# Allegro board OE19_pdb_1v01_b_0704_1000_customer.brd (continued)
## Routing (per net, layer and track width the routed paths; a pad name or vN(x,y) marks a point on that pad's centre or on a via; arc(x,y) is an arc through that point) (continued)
DELTA_L_85_10INCH_IN1_DN: length 254
  IN1 w0.114: v1(215.42,159.29) 215.56,159.43 215.56,161.63 216.19,162.26 216.56,164.33 216.44,164.5 212.99,165.11 212.69,165.53 212.87,166.52 213.29,166.82 217.24,166.12 217.37,166.22 217.49,166.86 217.39,166.99 213.14,167.74 212.85,168.16 213.02,169.15 213.45,169.44 217.64,168.71 217.77,168.8 217.88,169.44 217.79,169.58 213.21,170.38 212.91,170.8 213.12,171.96 213.54,172.26 217.61,171.54 217.74,171.63 217.86,172.27 217.76,172.4 213.1,173.23 212.81,173.65 212.98,174.64 213.4,174.93 217.61,174.19 217.75,174.28 217.86,174.92 217.77,175.06 213.22,175.86 212.93,176.28 213.1,177.27 213.52,177.56 217.6,176.85 217.73,176.94 217.84,177.58 217.75,177.71 213.19,178.52 212.9,178.94 213.07,179.93 213.49,180.22 217.58,179.5 217.71,179.59 217.83,180.23 217.73,180.37 213.24,181.16 212.94,181.58 213.12,182.57 213.54,182.87 217.62,182.15 217.75,182.24 217.87,182.88 217.77,183.01 213.24,183.81 212.95,184.23 213.12,185.22 213.54,185.52 217.64,184.8 217.77,184.89 217.89,185.53 217.79,185.66 213.18,186.48 212.88,186.9 213.06,187.89 213.48,188.18 217.58,187.46 217.71,187.55 217.83,188.19 217.74,188.32 213.17,189.13 212.88,189.55 213.05,190.54 213.48,190.84 217.64,190.1 217.77,190.19 217.88,190.84 217.79,190.97 213.19,191.78 212.89,192.2 213.07,193.19 213.49,193.49 217.52,192.77 217.66,192.87 217.77,193.51 217.68,193.64 213.16,194.44 212.87,194.86 213.04,195.85 213.47,196.14 217.56,195.42 217.69,195.51 217.8,196.15 217.71,196.29 213.19,197.08 212.9,197.51 213.07,198.49 213.49,198.79 217.59,198.07 217.72,198.16 217.83,198.8 217.74,198.93 213.22,199.73 212.93,200.15 213.1,201.14 213.52,201.44 217.63,200.71 217.76,200.81 217.88,201.45 217.78,201.58 213.23,202.38 212.93,202.8 213.11,203.79 213.53,204.09 217.62,203.37 217.75,203.46 217.87,204.1 217.78,204.23 213.22,205.04 212.92,205.46 213.1,206.45 213.52,206.74 217.52,206.04 217.65,206.13 217.77,206.77 217.67,206.9 213.19,207.69 212.9,208.11 213.07,209.1 213.5,209.4 217.59,208.68 217.72,208.77 217.84,209.41 217.75,209.54 213.18,210.35 212.89,210.77 213.06,211.76 213.48,212.05 217.61,211.33 217.75,211.42 217.86,212.06 217.77,212.19 213.17,213 212.87,213.42 213.05,214.41 213.47,214.71 217.59,213.98 217.72,214.08 217.84,214.72 217.74,214.85 213.17,215.66 212.87,216.08 213.05,217.07 213.47,217.36 217.55,216.64 217.68,216.74 217.79,217.38 217.7,217.51 213.17,218.31 212.88,218.73 213.05,219.72 213.48,220.01 215.32,219.69 215.45,219.78 215.59,220.57 215.59,223.11 v1(215.41,223.28)
  BOTTOM w0.099: J27.1 v1(215.41,223.28) ; J33.2 v1(215.42,159.29)
DELTA_L_85_10INCH_IN1_DP: length 254
  IN1 w0.114: v1(216.18,159.29) 215.99,159.48 215.99,161.45 216.59,162.05 217.01,164.43 216.69,164.89 213.24,165.5 213.14,165.63 213.26,166.28 213.39,166.37 217.34,165.67 217.76,165.97 217.94,166.96 217.64,167.38 213.39,168.13 213.3,168.26 213.41,168.9 213.55,168.99 217.74,168.25 218.16,168.55 218.33,169.54 218.04,169.96 213.46,170.77 213.37,170.9 213.51,171.71 213.64,171.81 217.71,171.09 218.13,171.38 218.31,172.37 218.01,172.79 213.35,173.62 213.26,173.75 213.37,174.39 213.5,174.48 217.71,173.74 218.14,174.04 218.31,175.02 218.01,175.45 213.47,176.25 213.38,176.38 213.49,177.02 213.62,177.11 217.7,176.4 218.12,176.69 218.29,177.68 218,178.1 213.44,178.91 213.35,179.04 213.46,179.68 213.59,179.77 217.68,179.05 218.1,179.35 218.28,180.33 217.98,180.76 213.49,181.55 213.39,181.68 213.51,182.32 213.64,182.42 217.72,181.7 218.14,181.99 218.32,182.98 218.02,183.4 213.49,184.2 213.4,184.33 213.51,184.97 213.64,185.07 217.74,184.35 218.16,184.64 218.34,185.63 218.04,186.05 213.43,186.87 213.33,187 213.45,187.64 213.58,187.73 217.68,187.01 218.1,187.3 218.28,188.29 217.98,188.71 213.42,189.52 213.33,189.65 213.44,190.29 213.58,190.38 217.74,189.65 218.16,189.95 218.34,190.94 218.04,191.36 213.44,192.17 213.34,192.3 213.46,192.94 213.59,193.04 217.62,192.32 218.05,192.62 218.22,193.61 217.93,194.03 213.41,194.83 213.32,194.96 213.43,195.6 213.57,195.69 217.66,194.97 218.08,195.27 218.25,196.25 217.96,196.68 213.44,197.47 213.35,197.61 213.46,198.25 213.59,198.34 217.69,197.62 218.11,197.91 218.29,198.9 217.99,199.32 213.47,200.12 213.38,200.25 213.49,200.89 213.62,200.99 217.73,200.26 218.15,200.56 218.33,201.55 218.03,201.97 213.48,202.77 213.39,202.9 213.5,203.55 213.63,203.64 217.72,202.92 218.14,203.21 218.32,204.2 218.02,204.62 213.46,205.43 213.37,205.56 213.49,206.2 213.62,206.29 217.62,205.59 218.04,205.88 218.22,206.87 217.92,207.29 213.44,208.08 213.35,208.21 213.46,208.86 213.6,208.95 217.69,208.23 218.11,208.52 218.29,209.51 217.99,209.93 213.43,210.74 213.34,210.87 213.45,211.51 213.58,211.6 217.71,210.88 218.14,211.17 218.31,212.16 218.02,212.58 213.42,213.39 213.32,213.52 213.44,214.17 213.57,214.26 217.69,213.53 218.11,213.83 218.29,214.82 217.99,215.24 213.42,216.05 213.32,216.18 213.44,216.82 213.57,216.91 217.65,216.19 218.07,216.49 218.24,217.48 217.95,217.9 213.42,218.7 213.33,218.83 213.44,219.47 213.58,219.56 215.42,219.24 215.84,219.53 216.02,220.53 216.02,223.13 v1(216.18,223.28)
  BOTTOM w0.099: J33.1 v1(216.18,159.29) ; J27.2 v1(216.18,223.28)
DELTA_L_85_10INCH_IN2_DN: length 254
  TOP w0.099: J31.2 v1(213.64,159.52) ; J25.1 v1(213.64,223.09)
  IN2 w0.114: v1(213.64,223.09) 213.47,222.93 213.47,220.82 213.65,219.77 213.79,219.68 215.63,220 216.05,219.71 216.22,218.72 215.93,218.29 211.4,217.5 211.31,217.36 211.43,216.72 211.56,216.63 215.63,217.35 216.06,217.05 216.23,216.06 215.94,215.64 211.36,214.84 211.27,214.7 211.38,214.06 211.51,213.97 215.63,214.7 216.05,214.4 216.23,213.41 215.93,212.99 211.34,212.18 211.24,212.05 211.36,211.41 211.49,211.31 215.62,212.04 216.04,211.75 216.22,210.76 215.92,210.34 211.36,209.53 211.27,209.4 211.38,208.76 211.51,208.66 215.61,209.39 216.03,209.09 216.2,208.1 215.91,207.68 211.43,206.89 211.34,206.76 211.45,206.12 211.58,206.02 215.59,206.73 216.01,206.44 216.18,205.45 215.89,205.02 211.33,204.22 211.24,204.09 211.35,203.45 211.48,203.35 215.57,204.08 215.99,203.78 216.17,202.79 215.87,202.37 211.32,201.57 211.23,201.43 211.34,200.79 211.47,200.7 215.58,201.42 216,201.13 216.18,200.14 215.88,199.72 211.36,198.92 211.27,198.79 211.38,198.15 211.51,198.06 215.61,198.78 216.03,198.48 216.21,197.49 215.91,197.07 211.39,196.27 211.3,196.14 211.41,195.5 211.55,195.41 215.64,196.13 216.06,195.83 216.23,194.84 215.94,194.42 211.43,193.63 211.33,193.49 211.45,192.85 211.58,192.76 215.62,193.47 216.04,193.18 216.21,192.19 215.92,191.77 211.31,190.95 211.22,190.82 211.33,190.18 211.46,190.09 215.63,190.82 216.05,190.53 216.22,189.54 215.93,189.12 211.37,188.31 211.28,188.18 211.39,187.54 211.52,187.45 215.62,188.17 216.05,187.87 216.22,186.88 215.93,186.46 211.31,185.65 211.22,185.52 211.33,184.88 211.46,184.78 215.56,185.51 215.98,185.21 216.16,184.22 215.86,183.8 211.33,183 211.24,182.87 211.35,182.23 211.48,182.13 215.56,182.85 215.99,182.56 216.16,181.57 215.87,181.15 211.37,180.35 211.28,180.22 211.39,179.58 211.52,179.49 215.61,180.21 216.03,179.91 216.21,178.92 215.91,178.5 211.35,177.7 211.26,177.57 211.37,176.93 211.51,176.83 215.58,177.55 216,177.26 216.18,176.27 215.88,175.84 211.37,175.05 211.28,174.92 211.39,174.28 211.53,174.18 215.61,174.91 216.04,174.61 216.21,173.62 215.92,173.2 211.37,172.4 211.28,172.27 211.39,171.62 211.53,171.53 215.56,172.24 215.98,171.95 216.19,170.79 215.89,170.37 211.31,169.56 211.22,169.43 211.33,168.79 211.47,168.69 215.72,169.44 216.14,169.15 216.17,168.97 216.31,168.16 216.02,167.74 211.77,166.99 211.68,166.85 211.79,166.21 211.92,166.12 215.84,166.81 216.26,166.52 216.44,165.53 216.14,165.1 212.43,164.45 212.34,164.32 212.66,162.48 213.47,161.67 213.47,159.69 v1(213.64,159.52)
DELTA_L_85_10INCH_IN2_DP: length 254
  TOP w0.099: J25.2 v1(212.87,223.09) ; J31.1 v1(212.88,159.52)
  IN2 w0.114: v1(212.88,159.52) 213.04,159.69 213.04,161.5 212.26,162.28 211.89,164.42 212.18,164.84 215.89,165.49 215.99,165.63 215.87,166.27 215.74,166.36 211.82,165.67 211.4,165.96 211.22,166.95 211.52,167.38 215.77,168.12 215.86,168.26 215.75,168.9 215.62,168.99 211.37,168.24 210.94,168.54 210.77,169.53 211.06,169.95 215.64,170.76 215.74,170.89 215.59,171.7 215.46,171.79 211.43,171.08 211,171.38 210.83,172.37 211.13,172.79 215.67,173.59 215.76,173.72 215.65,174.36 215.51,174.45 211.43,173.73 211,174.03 210.83,175.02 211.13,175.44 215.63,176.23 215.72,176.37 215.61,177.01 215.48,177.1 211.41,176.38 210.98,176.68 210.81,177.67 211.11,178.09 215.66,178.89 215.75,179.02 215.64,179.67 215.51,179.76 211.42,179.04 211,179.33 210.82,180.32 211.12,180.74 215.62,181.54 215.71,181.67 215.6,182.31 215.46,182.4 211.38,181.68 210.96,181.98 210.78,182.97 211.08,183.39 215.61,184.19 215.7,184.32 215.59,184.96 215.46,185.05 211.36,184.33 210.94,184.63 210.77,185.62 211.06,186.04 215.68,186.85 215.77,186.98 215.66,187.63 215.52,187.72 211.42,187 211,187.29 210.82,188.28 211.12,188.7 215.68,189.51 215.77,189.64 215.66,190.28 215.53,190.37 211.36,189.64 210.94,189.93 210.77,190.92 211.06,191.34 215.67,192.16 215.76,192.29 215.65,192.93 215.52,193.02 211.48,192.31 211.06,192.61 210.88,193.59 211.18,194.02 215.69,194.81 215.78,194.94 215.67,195.59 215.54,195.68 211.45,194.96 211.03,195.25 210.85,196.24 211.15,196.66 215.66,197.46 215.76,197.59 215.64,198.23 215.51,198.33 211.41,197.6 210.99,197.9 210.82,198.89 211.11,199.31 215.63,200.11 215.73,200.24 215.61,200.88 215.48,200.97 211.37,200.25 210.95,200.54 210.77,201.53 211.07,201.96 215.63,202.76 215.72,202.89 215.61,203.53 215.47,203.62 211.38,202.9 210.96,203.2 210.78,204.19 211.08,204.61 215.64,205.41 215.73,205.55 215.62,206.19 215.49,206.28 211.48,205.57 211.06,205.87 210.88,206.86 211.18,207.28 215.66,208.07 215.75,208.2 215.64,208.84 215.51,208.94 211.41,208.21 210.99,208.51 210.81,209.5 211.11,209.92 215.67,210.73 215.77,210.86 215.65,211.5 215.52,211.59 211.39,210.86 210.97,211.16 210.79,212.15 211.09,212.57 215.69,213.38 215.78,213.51 215.67,214.15 215.53,214.25 211.41,213.52 210.99,213.81 210.82,214.8 211.11,215.23 215.69,216.03 215.78,216.16 215.67,216.81 215.53,216.9 211.46,216.18 211.04,216.48 210.86,217.46 211.16,217.89 215.68,218.68 215.77,218.82 215.66,219.46 215.53,219.55 213.69,219.22 213.26,219.52 213.04,220.78 213.04,222.93 v1(212.87,223.09)
DELTA_L_85_10INCH_TOP_DN: length 254
  TOP w0.099: J26.1 213.04,240.82 213.04,244.24 213.62,244.83 213.99,244.89 214.07,245.01 213.95,245.66 213.84,245.74 211.02,245.24 210.66,245.49 210.5,246.44 210.75,246.79 215.48,247.63 215.56,247.74 215.44,248.4 215.33,248.48 211.05,247.72 210.7,247.97 210.53,248.92 210.78,249.27 215.44,250.09 215.52,250.21 215.4,250.86 215.29,250.94 211.05,250.19 210.7,250.44 210.53,251.39 210.78,251.74 215.47,252.57 215.55,252.68 215.43,253.34 215.32,253.42 211,252.66 210.65,252.91 210.48,253.85 210.73,254.21 215.49,255.05 215.57,255.16 215.45,255.82 215.34,255.9 211.03,255.14 210.68,255.39 210.51,256.33 210.76,256.68 215.45,257.51 215.53,257.63 215.41,258.28 215.3,258.36 211.01,257.61 210.65,257.85 210.49,258.8 210.73,259.15 215.47,259.99 215.55,260.1 215.44,260.76 215.32,260.84 211.04,260.08 210.69,260.33 210.52,261.28 210.77,261.63 215.49,262.46 215.57,262.58 215.45,263.23 215.34,263.31 211.06,262.56 210.7,262.81 210.54,263.75 210.78,264.11 215.49,264.94 215.57,265.05 215.46,265.71 215.34,265.79 211.02,265.03 210.66,265.27 210.5,266.22 210.75,266.57 215.5,267.41 215.58,267.52 215.46,268.18 215.35,268.26 211.01,267.5 210.66,267.75 210.49,268.69 210.74,269.04 215.45,269.87 215.53,269.99 215.41,270.64 215.3,270.73 211.05,269.98 210.69,270.22 210.53,271.17 210.78,271.52 215.45,272.35 215.53,272.46 215.41,273.12 215.3,273.2 211.07,272.45 210.71,272.7 210.54,273.65 210.79,274 215.45,274.82 215.53,274.93 215.41,275.59 215.3,275.67 211.02,274.92 210.67,275.16 210.5,276.11 210.75,276.46 215.44,277.29 215.52,277.41 215.41,278.06 215.29,278.14 211.05,277.39 210.7,277.64 210.53,278.59 210.78,278.94 215.48,279.77 215.56,279.88 215.44,280.54 215.33,280.62 211.05,279.87 210.69,280.11 210.53,281.06 210.77,281.41 215.44,282.24 215.52,282.35 215.4,283.01 215.29,283.09 211.06,282.34 210.71,282.59 210.54,283.53 210.79,283.89 215.43,284.71 215.51,284.82 215.39,285.48 215.28,285.56 211.05,284.81 210.7,285.06 210.61,285.53 210.53,286.01 210.78,286.36 215.48,287.19 215.56,287.3 215.44,287.96 215.33,288.04 211.06,287.29 210.7,287.53 210.62,288.01 210.54,288.48 210.78,288.83 215.49,289.66 215.57,289.78 215.45,290.43 215.34,290.51 211.07,289.76 210.72,290.01 210.63,290.48 210.55,290.95 210.8,291.31 215.45,292.13 215.53,292.24 215.42,292.9 215.3,292.98 211.09,292.24 210.73,292.48 210.57,293.43 210.81,293.78 215.45,294.6 215.55,294.74 215.44,295.36 215.3,295.45 213.41,295.12 211.52,294.79 211.17,295.03 211,295.98 211.25,296.33 213.09,296.66 213.17,296.77 213.04,297.51 213.04,300.61 J32.2
DELTA_L_85_10INCH_TOP_DP: length 254
  TOP w0.099: J26.2 213.39,240.82 213.39,244.1 213.8,244.5 214.19,244.57 214.44,244.92 214.28,245.87 213.92,246.11 211.1,245.62 210.99,245.7 210.87,246.35 210.95,246.47 215.68,247.3 215.93,247.66 215.77,248.6 215.41,248.85 211.14,248.1 211.02,248.18 210.91,248.83 210.99,248.95 215.64,249.77 215.89,250.12 215.72,251.07 215.37,251.32 211.13,250.57 211.02,250.65 210.9,251.31 210.98,251.42 215.68,252.25 215.92,252.6 215.76,253.55 215.4,253.79 211.09,253.03 210.97,253.11 210.86,253.77 210.94,253.88 215.69,254.72 215.94,255.08 215.77,256.02 215.42,256.27 211.11,255.51 211,255.59 210.94,255.92 210.88,256.25 210.96,256.36 215.66,257.19 215.9,257.54 215.74,258.49 215.38,258.74 211.09,257.98 210.98,258.06 210.86,258.72 210.94,258.83 215.68,259.67 215.93,260.02 215.76,260.96 215.41,261.21 211.12,260.46 211.01,260.54 210.89,261.19 210.97,261.31 215.69,262.14 215.94,262.5 215.78,263.44 215.42,263.69 211.14,262.93 211.03,263.01 210.91,263.67 210.99,263.78 215.7,264.61 215.94,264.97 215.78,265.91 215.42,266.16 211.1,265.4 210.99,265.48 210.87,266.14 210.95,266.25 215.7,267.09 215.95,267.44 215.78,268.39 215.43,268.63 211.1,267.87 210.98,267.95 210.87,268.61 210.95,268.72 215.65,269.55 215.9,269.91 215.74,270.85 215.38,271.1 211.13,270.35 211.02,270.43 210.9,271.09 210.98,271.2 215.65,272.02 215.9,272.38 215.73,273.32 215.38,273.57 211.15,272.82 211.03,272.9 210.92,273.56 211,273.68 215.66,274.5 215.9,274.85 215.74,275.8 215.38,276.04 211.11,275.29 210.99,275.37 210.88,276.03 210.96,276.14 215.65,276.97 215.9,277.32 215.73,278.27 215.38,278.52 211.13,277.77 211.02,277.85 210.9,278.5 210.98,278.62 215.68,279.45 215.93,279.8 215.77,280.75 215.41,280.99 211.13,280.24 211.02,280.32 210.9,280.98 210.98,281.09 215.64,281.91 215.89,282.27 215.72,283.21 215.37,283.46 211.15,282.71 211.03,282.79 210.92,283.45 211,283.57 215.63,284.38 215.88,284.74 215.71,285.68 215.36,285.93 211.13,285.19 211.02,285.27 210.9,285.92 210.98,286.04 215.68,286.87 215.93,287.22 215.77,288.16 215.41,288.41 211.14,287.66 211.03,287.74 210.91,288.4 210.99,288.51 215.69,289.34 215.94,289.69 215.77,290.64 215.42,290.89 211.15,290.13 211.04,290.21 210.92,290.87 211,290.98 215.66,291.81 215.91,292.16 215.74,293.1 215.38,293.35 211.17,292.61 211.05,292.69 210.94,293.35 211.02,293.46 215.66,294.28 215.92,294.65 215.76,295.56 215.39,295.83 211.61,295.16 211.49,295.24 211.38,295.9 211.46,296.01 213.29,296.33 213.54,296.69 213.39,297.54 213.39,300.61 J32.1
FM_BBU_PRSNT_N: length 155
  IN2 w0.127: J1.B7 189.31,149.15 189.31,126.48 155.37,92.54 v1(155.37,24.02) 155.57,24.02 163.46,16.13 163.46,14.04 J9.I8
FM_BMC_SLED1_READY_N: length 155.5
  IN1 w0.127: J1.C8 189.74,147.9 189.74,124.91 165.51,100.68 v1(165.51,67.47) 165.51,67.08 165.03,66.6 165.03,65.32 162.56,62.85 162.56,28.53 167.48,23.61 167.48,20.63 168.89,19.23 168.89,8.76 168.88,8.75 168.88,8.18 J9.E6
FM_BMC_SLED2_READY_N: length 149
  IN1 w0.127: J1.H3 179.72,140.78 179.72,135.11 157.12,112.51 157.12,24.29 v1(159.58,21.83)
  BOTTOM w0.114: J9.F6 167.18,10.12 167.18,17.93 163.28,21.83 v1(159.58,21.83)
FM_BMC_SLED3_READY_N: length 153.4
  IN2 w0.127: v1(161.52,27.54) 156.87,32.18 156.87,92 191.27,126.39 191.27,143.69 J1.F8
  BOTTOM w0.114: J9.G6 167.45,11.25 167.45,20.01 162.89,24.57 162.89,26.17 v1(161.52,27.54)
FM_BMC_SLED4_READY_N: length 142.3
  IN1 w0.127: v1(180.57,132.19) 180.57,130.3 180.94,129.92 180.94,126.9 157.98,103.94 v1(157.98,28.94)
  BOTTOM w0.114: J1.K3 181.13,136.73 181.13,133.89 180.57,133.32 v1(180.57,132.19) ; J9.H6 167.71,12.39 167.71,20.54 167.7,20.57 164.82,23.45 164.82,25.98 161.86,28.94 v1(157.98,28.94)
FM_BMC_SLED5_READY_N: length 141
  IN1 w0.127: v1(164.31,28.36) 163.46,29.21 163.46,61.43 184.46,82.43 v1(184.46,113.53)
  IN2 w0.127: v1(164.31,28.36) 165.05,27.63 165.05,24.08 169.2,19.93 169.2,14.1 J9.I6
  BOTTOM w0.114: J1.I8 189.67,139.43 189.67,133.38 189.4,132.8 184.46,127.86 v1(184.46,113.53)
FM_PSU1_PRSNT_N: length 23.9
  TOP w0.114: J9.G8 163.72,10.4 160.87,13.24 160.87,16.54 158.18,19.24 149.61,19.24 147.87,20.97 R18.2 R33.2
FM_PSU1_PRSNT_R_N: length 93.8
  TOP w0.114: v1(147.07,19.91) R18.1
  BOTTOM w0.114: JP1.S8 61.81,10.03 68.5,10.03 74.73,16.26 80.63,16.26 82.75,18.38 124.45,18.38 125.11,17.72 132.53,17.72 133.27,16.99 138.38,16.99 140.36,18.97 146.14,18.97 v1(147.07,19.91)
FM_PSU2_PRSNT_N: length 22.7
  TOP w0.114: v1(151.11,21.7) 149.34,21.7 R35.2 R19.2 ; v1(156.45,22.33) 158.05,22.33 162.65,17.72 162.65,15.66 163.72,14.6 J9.J8
  BOTTOM w0.114: v1(156.45,22.33) 155.82,21.7 v1(151.11,21.7)
FM_PSU2_PRSNT_R_N: length 22.7
  TOP w0.114: R19.1 v1(145.52,24.21)
  IN1 w0.127: JP2.S8 138.77,10.66 139.29,10.14 144.15,10.14 145.07,11.05 145.07,23.75 v1(145.52,24.21)
FM_RMC_GPIO_0: length 144.3
  TOP w0.114: v1(162.4,23.86) 167.17,19.09 167.17,15.73 J9.J6
  IN1 w0.127: v1(162.4,23.86) 160,26.26 160,63.38 162.87,66.25 162.87,102.78 185.73,125.64 185.73,143.69 J1.F6
FM_RMC_GPIO_1: length 139.9
  TOP w0.114: v1(163.95,24.52) 163.95,23.62 167.45,20.12 167.45,17.88 167.45,17.87 167.45,16.85 J9.K6
  IN1 w0.127: J1.H6 187.65,140.51 187.65,125.09 163.8,101.24 163.8,65.82 161.39,63.41 161.39,28.46 162.94,26.92 162.94,25.53 v1(163.95,24.52)
FM_RMC_GPIO_2: length 138.9
  TOP w0.114: J9.L6 167.71,17.99 167.71,21.49 165.19,24.01 165.19,25.06 164.09,26.15 v1(161.62,26.15)
  IN1 w0.127: v1(161.62,26.15) 160.62,27.15 160.62,63.53 163.37,66.29 163.37,101.73 187.3,125.65 187.3,139.46 J1.I6
FM_SLED1_PRSNT_N: length 146.4
  IN1 w0.127: J9.L7 166.3,24.2 162.13,28.37 162.13,63.16 164.39,65.42 164.39,69.6 v1(164.81,70.02) 164.39,70.44 164.39,100.56 189.31,125.49 189.31,148.87 J1.B8
FM_SLED2_PRSNT_N: length 162.1
  IN1 w0.127: J1.G3 179.32,141.78 179.32,135.51 156.55,112.75 156.55,23.84 v1(157.07,23.32) 159.47,20.93 164.9,20.93 165.18,20.65 165.18,1.13 165.3,1 167.3,1 J9.A6
FM_SLED3_PRSNT_N: length 161.2
  IN2 w0.127: J1.E8 191.6,144.76 191.6,125.81 161.18,95.39 v1(161.18,94.74) 157.84,91.41 157.84,32.81 162.5,28.16 162.5,24.84 167.67,19.67 167.67,4.03 J9.B6
FM_SLED4_PRSNT_N: length 157
  IN1 w0.127: J9.C6 167.19,3.69 167.19,1.94 166.64,1.39 165.9,1.39 165.58,1.71 165.58,20.91 164.71,21.77 161.78,21.77 158.5,25.05 158.5,103.72 181.63,126.84 v1(181.63,132.95)
  BOTTOM w0.114: J1.J3 181.63,137.63 v1(181.63,132.95)
FM_SLED5_PRSNT_N: length 149.8
  IN1 w0.127: v1(183.55,114.27) 183.55,82.71 163.05,62.21 163.05,28.75 168.42,23.38 169.22,19.36 169.22,8.62 169.21,8.61 169.21,8.04 169.05,7.88 169.05,6.95 J9.D6
  BOTTOM w0.114: v1(183.55,114.27) 183.24,114.58 183.24,128.3 189.41,134.47 189.41,140.57 J1.H8
FRU_A0: length 7.8
  TOP w0.114: R1119.1 R1118.2 143.15,73.47 143.71,72.92 U32.1
FRU_A1: length 7.7
  TOP w0.114: R1116.1 R1115.2 148.33,71.38 148.6,71.65 U32.2
FRU_A2: length 7.6
  TOP w0.114: U32.3 143.71,70.38 143.56,70.24 R1112.2 R324.1
FRU_WP: length 6.1
  TOP w0.114: U32.7 156.69,71.65 157.12,72.08 158.1,72.08 158.54,71.65 159.18,71.65 159.2,71.67 R1120.2 R1121.1
IRQ_PSU1_ALERT_N: length 27.1
  TOP w0.114: J9.H7 165.27,12.93 165.27,13.63 164.89,14.01 163.5,14.01 162.19,15.31 162.19,17.38 157.99,21.58 155.6,21.58 152.3,24.88 152.3,27.56 R12.2 R28.2
IRQ_PSU1_ALERT_R_N: length 103.6
  TOP w0.114: R12.1 149.14,29.24 v1(148.94,29.04)
  BOTTOM w0.114: v1(148.94,29.04) 148.94,23.85 146.51,21.42 137.91,21.42 135.41,18.92 126.43,18.92 124.9,20.45 82.27,20.45 80.12,18.3 60.4,18.3 57.73,15.63 JP1.S19
IRQ_PSU2_ALERT_N: length 25.4
  TOP w0.114: R14.2 R30.2 150.91,31.34 163.16,19.09 163.16,17.95 163.16,17.94 163.16,16.15 164.08,15.22 164.99,15.22 165.52,14.7 J9.J7
IRQ_PSU2_ALERT_R_N: length 31.2
  TOP w0.114: v1(149.83,33.54) R14.1
  BOTTOM w0.114: v1(149.83,33.54) 149.83,21.05 147.06,18.28 140.69,18.28 139.01,16.61 136.79,16.61 136.23,16.04 JP2.S19
IRQ_RMC_ALERT_N: length 144.4
  IN1 w0.127: v1(159.41,25.65) 159.41,63.4 162.34,66.33 162.34,103.22 185.25,126.13 185.25,129.51 185.3,129.56 185.3,144.66 J1.E6
  IN2 w0.127: v1(159.41,25.65) 167.02,18.04 167.02,16.82 J9.K7
LAN_SLED1_MDIN0: length 151.7
  BOTTOM w0.099: J1.C10 195.02,149.18 195.76,149.18 196.75,148.19 196.75,135.92 195.76,130.95 195.76,130.95 195.48,129.54 193.6,123.34 193.6,116.21 190.02,79.8 186.43,43.38 185.74,39.91 182.59,7.9 180.48,3.44 180.01,2.98 178.82,2.98 J9.B1
LAN_SLED1_MDIN1: length 144.2
  IN2 w0.114: v1(183.84,33.67) 183.54,33.38 183.54,32.4 183.41,32.07 183.56,31.69 183.43,31.37 183.05,31.21 182.92,30.89 183.07,30.5 182.94,30.18 182.56,30.02 178.82,21 177.83,20.01 177.54,19.3 177.54,18.95 177.83,18.66 177.83,18.31 177.54,18.01 177.54,7.33 177.65,7.21 177.81,7.21 J9.E1
  BOTTOM w0.099: v1(183.84,33.67) 183.5,34.01 183.5,34.64 183.5,34.64 187.82,78.45 189.68,116.24 194.96,133.67 195.73,134.61 195.97,135.39 195.85,136.6 196.09,137.38 196.09,144.57 195.33,145.34 195.02,145.34 J1.E10
LAN_SLED1_MDIN2: length 143.4
  BOTTOM w0.099: J1.B9 193.02,150.48 193.16,150.48 193.31,150.34 193.31,135.95 187.03,120.79 184.13,61.72 181.35,33.52 181.35,32.33 181.96,26.17 181.43,15.54 179.97,12 179.34,11.38 178.82,11.38 J9.H1
LAN_SLED1_MDIN3: length 135.4
  BOTTOM w0.099: J1.E9 191.98,146.28 191.84,146.28 191.73,146.18 191.73,135.41 186.1,123.5 182.64,53.14 181.21,38.65 180.29,33.98 181.14,25.29 180.2,15.78 179.65,15.22 178.82,15.22 J9.J1
LAN_SLED1_MDIP0: length 153.4
  BOTTOM w0.099: J9.A1 178.82,2.62 180.16,2.62 180.77,3.24 182.93,7.8 186.09,39.86 186.78,43.33 190.37,79.76 190.37,79.76 193.96,116.19 193.96,123.29 195.83,129.46 196.08,130.74 196.37,130.93 196.42,131.22 196.23,131.5 196.36,132.13 196.64,132.32 196.7,132.61 196.51,132.89 196.59,133.27 196.87,133.46 196.93,133.75 196.74,134.04 197.1,135.85 197.1,135.86 197.1,148.34 195.9,149.54 195.02,149.54 J1.B10
LAN_SLED1_MDIP1: length 143.6
  IN2 w0.114: J9.D1 177.81,6.79 177.47,6.79 177.11,7.15 177.11,19.39 177.47,20.25 178.46,21.24 182.16,30.19 183.11,32.48 183.11,33.38 v1(182.82,33.67)
  BOTTOM w0.099: v1(182.82,33.67) 183.15,34.01 183.15,34.66 187.47,78.47 189.32,116.3 194.65,133.84 195.42,134.78 195.61,135.43 195.49,136.63 195.73,137.43 195.73,144.43 195.18,144.98 195.02,144.98 J1.F10
LAN_SLED1_MDIP2: length 144.5
  BOTTOM w0.099: J9.G1 178.82,11.02 179.49,11.02 180.27,11.8 181.78,15.46 182.31,26.18 181.7,32.35 181.7,33.5 184.48,61.7 187.38,120.71 193.66,135.87 193.66,135.87 193.66,150.49 193.31,150.84 193.02,150.84 J1.A9
LAN_SLED1_MDIP3: length 135.6
  BOTTOM w0.099: J1.D9 191.98,146.64 191.69,146.64 191.38,146.32 191.38,135.49 191.25,135.22 190.93,135.11 190.8,134.84 190.92,134.52 185.75,123.59 182.29,53.17 180.87,38.7 179.93,34 180.79,25.29 179.87,15.94 179.51,15.58 178.82,15.58 J9.K1
LAN_SLED2_MDIN0: length 150.1
  TOP w0.099: v1(174.09,124.2) 173.76,124.53 173.76,149.18 175.06,150.48 175.98,150.48 J1.B1
  BOTTOM w0.099: J9.C2 175.78,4.28 175.64,4.28 175.55,4.37 175.55,19.43 177.96,31.55 176.93,36.7 176.15,44.68 175.03,67.43 175.03,68.73 176.17,91.91 174.28,111.09 173.76,121.67 173.76,123.87 v1(174.09,124.2)
LAN_SLED2_MDIN1: length 141.4
  TOP w0.099: v1(179.25,37.37) 178.92,37.04 178.92,36.55 175.95,21.58 175.87,21.2 176.06,20.92 176,20.62 175.72,20.44 175.55,19.55 175.55,8.57 175.64,8.48 175.78,8.48 J9.F2 ; v1(175.74,127.3) 175.41,127.63 175.41,145.85 175.84,146.28 175.98,146.28 J1.E1
  BOTTOM w0.099: v1(175.74,127.3) 175.41,126.97 175.41,125.97 176.31,107.57 177.79,92.53 177.79,90.93 176.48,64.28 177.65,40.5 178.14,39.59 178.67,39.06 178.92,38.44 178.92,37.7 v1(179.25,37.37)
LAN_SLED2_MDIN2: length 140.7
  IN1 w0.114: J9.I2 176.79,12.71 176.95,12.71 177.16,12.93 177.16,18.34 179.14,28.3 179.98,36.8 179.98,37.56 179.88,37.8 178.56,39.78 178.56,40.48 v1(178.27,40.78)
  IN2 w0.114: v1(176.96,130.29) 177.14,130.29 177.26,130.41 177.26,131.13 177.99,132.88 178.71,133.61 179.31,135.04 179.31,149 179.19,149.12 178.96,149.12 J1.C2
  BOTTOM w0.099: v1(176.96,130.29) 177.3,129.96 177.3,129.22 177.05,128.98 177.05,128.68 177.3,128.44 177.3,128.02 177.05,127.78 177.05,127.49 177.3,127.24 177.3,124.54 179.68,100.28 177.71,60 178.6,41.87 178.6,41.11 v1(178.27,40.78)
LAN_SLED2_MDIN3: length 132.9
  TOP w0.099: v1(179.57,42.66) 179.9,42.33 179.9,41.2 180,40.72 179.81,40.43 179.87,40.14 180.15,39.95 180.37,38.85 180.37,38.55 180.13,38.31 180.13,38.02 180.37,37.77 180.37,36.18 177.24,20.45 177.24,20.15 177,19.91 177,19.61 177.24,19.37 177.24,17.16 176.96,16.88 176.82,16.88 J9.L2 ; v1(178.93,126.82) 179.26,127.15 179.26,144.88 179.16,144.98 179.02,144.98 J1.F2
  BOTTOM w0.099: v1(178.93,126.82) 179.26,126.49 179.26,125.49 179.33,124.2 179.1,123.94 179.11,123.65 179.36,123.42 179.38,123.12 179.15,122.87 179.16,122.57 179.42,122.34 179.43,122.04 179.2,121.79 179.22,121.49 179.47,121.27 179.5,120.69 179.27,120.44 179.28,120.14 179.54,119.91 179.9,112.46 179.9,110.66 180.9,100.48 180.9,98.64 180.46,89.67 180.21,89.44 180.2,89.14 180.43,88.89 180.41,88.59 180.16,88.36 180.14,88.07 180.37,87.81 179.8,76.19 180.72,57.48 180.72,56.22 179.9,47.91 179.9,42.99 v1(179.57,42.66)
LAN_SLED2_MDIP0: length 151.7
  TOP w0.099: J1.A1 175.98,150.84 174.92,150.84 173.41,149.33 173.41,124.53 v1(173.08,124.2)
  BOTTOM w0.099: v1(173.08,124.2) 173.41,123.87 173.41,121.66 173.93,111.07 175.81,91.9 174.68,68.74 174.68,67.42 175.79,44.65 176.58,36.65 177.6,31.55 177.08,28.96 176.8,28.78 176.74,28.48 176.93,28.2 176.74,27.26 176.46,27.07 176.4,26.78 176.59,26.5 175.19,19.46 175.19,4.22 175.49,3.92 175.78,3.92 J9.B2
LAN_SLED2_MDIP1: length 142.4
  TOP w0.099: J1.D1 175.98,146.64 175.69,146.64 175.05,146 175.05,127.63 v1(174.72,127.3) ; J9.E2 175.78,8.12 175.49,8.12 175.19,8.42 175.19,19.6 175.63,21.81 178.57,36.58 178.57,37.04 v1(178.24,37.37)
  BOTTOM w0.099: v1(174.72,127.3) 175.05,126.97 175.05,125.96 175.96,107.54 177.44,92.51 177.44,90.93 176.13,64.28 177.3,40.41 177.85,39.38 178.37,38.86 178.57,38.37 178.57,37.7 v1(178.24,37.37)
LAN_SLED2_MDIP2: length 141.9
  IN1 w0.114: v1(179.28,40.78) 178.99,40.48 178.99,39.91 179.32,39.41 179.66,39.34 179.82,39.09 179.75,38.76 180.26,38 180.41,37.64 180.41,36.77 179.57,28.24 177.59,18.29 177.59,12.75 177.13,12.29 176.79,12.29 J9.H2
  IN2 w0.114: J1.B2 178.99,149.57 179.34,149.57 179.73,149.17 179.73,134.96 179.08,133.37 178.35,132.64 177.68,131.04 177.68,130.41 177.8,130.29 v1(177.98,130.29)
  BOTTOM w0.099: v1(179.28,40.78) 178.95,41.11 178.95,41.88 178.06,60 180.04,100.29 177.65,124.56 177.65,129.96 v1(177.98,130.29)
LAN_SLED2_MDIP3: length 134
  TOP w0.099: J9.K2 176.82,16.52 177.11,16.52 177.6,17.01 177.6,20.41 180.72,36.13 180.72,36.13 180.72,38.89 180.26,41.24 180.26,42.33 v1(180.59,42.66) ; v1(179.95,126.82) 179.62,127.15 179.62,131.96 179.86,132.2 179.86,132.49 179.62,132.74 179.62,133.03 179.86,133.27 179.86,133.57 179.62,133.81 179.62,134.2 179.86,134.44 179.86,134.74 179.62,134.98 179.62,145.03 179.31,145.34 179.02,145.34 J1.E2
  BOTTOM w0.099: v1(180.59,42.66) 180.26,42.99 180.26,47.88 180.46,49.93 180.72,50.15 180.75,50.45 180.53,50.71 180.56,51.01 180.83,51.22 180.86,51.52 180.64,51.78 181.07,56.2 181.07,57.49 180.16,76.17 180.95,92.3 181.2,92.53 181.21,92.82 180.99,93.08 181.04,94.22 181.29,94.45 181.31,94.74 181.08,95 181.26,98.63 181.26,100.5 180.26,110.68 180.26,112.47 180.14,114.74 180.37,114.99 180.36,115.29 180.11,115.51 180.09,115.81 180.32,116.07 180.31,116.36 180.05,116.59 179.62,125.53 179.62,126.49 v1(179.95,126.82)
LAN_SLED3_MDIN0: length 139.2
  TOP w0.099: J9.A3 173.78,2.62 173.49,2.62 173.06,3.05 173.06,20.96 172.49,32.47 172.49,33.35 172.88,37.26 173.06,40.92 173.06,44.27 188.46,121.69 188.46,121.69 193.38,133.58 193.38,136.63 193.69,136.94 193.98,136.94 J1.K10
LAN_SLED3_MDIN1: length 141
  TOP w0.099: J1.H10 195.02,141.14 196.08,141.14 196.54,140.67 196.54,135.6 190.18,120.25 174.83,43.08 174.83,38.31 v1(175.2,37.93)
  IN1 w0.114: v1(175.2,37.93) 174.91,37.64 174.91,37.26 174.69,36.73 174.35,36.38 173.85,35.2 173.18,33.56 173.11,33.22 173.34,32.87 173.27,32.53 172.93,32.3 172.74,31.36 172.71,31.03 172.97,30.71 172.94,30.36 172.62,30.09 172.21,26 173.48,19.62 173.48,7.38 173.65,7.21 173.81,7.21 J9.E3
LAN_SLED3_MDIN2: length 136.5
  TOP w0.099: v1(174.13,34.17) 174.46,34.5 174.46,34.9 174.82,35.76 175.74,37.14 175.83,37.36 176.36,42.68 176.88,47.99 190.27,115.32 190.97,116.99 192.05,118.08 192.26,118.58 192.26,118.91 v1(191.93,119.24)
  IN1 w0.114: J9.H3 174.79,11.41 174.95,11.41 175.08,11.55 175.08,19.21 175.35,20.57 175.86,25.72 175.6,26.03 175.63,26.38 175.95,26.65 175.99,27.09 175.73,27.41 175.77,27.76 176.08,28.02 176.25,29.65 175.88,31.49 175.56,32.26 174.43,33.39 174.43,33.87 v1(174.13,34.17) ; v1(191.93,119.24) 192.22,119.53 192.22,121.8 192.83,128.02 193.26,134.97 193.26,141.93 193.15,142.05 192.99,142.05 J1.H9
LAN_SLED3_MDIN3: length 129.1
  TOP w0.099: v1(192.9,116.52) 192.59,116.21 192.59,115.81 192.08,114.58 192.08,114.25 177.59,41.38 177.59,36.39 176.76,34.38 175,32.63 174.84,32.23 174.84,31.7 v1(175.17,31.37)
  IN2 w0.114: v1(175.17,31.37) 174.87,31.08 174.87,29.77 175.55,22.91 175.55,15.61 175.13,15.19 174.79,15.19 J9.J3 ; J1.J9 192.99,138.27 193.33,138.27 193.69,137.91 193.69,136.47 193.08,130.23 194.04,120.47 194.04,119.04 193.87,118.63 192.79,117.56 192.61,117.12 192.61,116.82 v1(192.9,116.52)
LAN_SLED3_MDIP0: length 138.2
  TOP w0.099: J1.L10 193.98,136.58 193.84,136.58 193.74,136.48 193.74,133.51 188.8,121.58 173.41,44.24 173.41,40.91 173.23,37.24 172.85,33.33 172.85,32.48 173.41,20.97 173.41,19.9 173.65,19.66 173.65,19.36 173.41,19.12 173.41,3.2 173.64,2.98 173.78,2.98 J9.B3
LAN_SLED3_MDIP1: length 141.2
  TOP w0.099: J1.I10 195.02,140.78 195.93,140.78 196.19,140.53 196.19,139.63 195.95,139.39 195.95,139.09 196.19,138.85 196.19,138.55 195.95,138.31 195.95,138.01 196.19,137.77 196.19,137.47 195.95,137.23 195.95,136.94 196.19,136.69 196.19,135.67 189.84,120.35 174.48,43.12 174.48,38.22 v1(174.19,37.93)
  IN1 w0.114: v1(174.19,37.93) 174.48,37.64 174.48,37.35 174.33,36.97 173.98,36.62 173.52,35.51 172.77,33.69 172.32,31.44 171.78,25.98 173.06,19.57 173.06,7.21 173.47,6.79 173.81,6.79 J9.D3
LAN_SLED3_MDIP2: length 137.4
  TOP w0.099: v1(175.15,34.17) 174.82,34.5 174.82,34.83 175.14,35.6 176.05,36.97 176.18,37.28 177.23,47.94 190.61,115.22 191.27,116.79 192.35,117.88 192.61,118.51 192.61,118.91 v1(192.94,119.24)
  IN1 w0.114: J9.G3 174.79,10.99 175.13,10.99 175.51,11.37 175.51,19.17 175.77,20.51 176.49,27.8 176.68,29.67 176.29,31.61 175.92,32.5 174.86,33.57 174.86,33.88 v1(175.15,34.17) ; J1.G9 192.99,142.47 193.33,142.47 193.69,142.11 193.69,134.94 193.69,134.94 193.26,127.98 192.65,121.78 192.65,119.53 v1(192.94,119.24)
LAN_SLED3_MDIP3: length 128.1
  TOP w0.099: v1(191.89,116.52) 192.24,116.17 192.24,115.88 191.73,114.65 191.73,114.28 180.86,59.65 177.24,41.41 177.24,36.46 176.46,34.58 174.7,32.83 174.48,32.3 174.48,31.7 v1(174.15,31.37)
  IN2 w0.114: J1.K9 192.99,137.85 193.15,137.85 193.26,137.73 193.26,136.49 192.65,130.23 193.61,120.45 193.61,119.13 193.51,118.88 192.43,117.8 192.18,117.2 192.18,116.82 v1(191.89,116.52) ; J9.K3 174.79,15.61 174.95,15.61 175.12,15.79 175.12,19.24 174.83,19.53 174.83,19.88 175.12,20.18 175.12,20.53 174.83,20.82 174.83,21.17 175.12,21.46 175.12,22.89 174.45,29.75 174.45,31.08 v1(174.15,31.37)
LAN_SLED4_MDIN0: length 144.1
  BOTTOM w0.099: J9.B4 172.82,3.92 173.11,3.92 173.59,4.4 173.59,18.48 172.15,25.71 172.15,25.71 171.75,27.74 168.1,36.56 168.23,36.88 168.11,37.15 167.8,37.28 167.52,37.94 166.4,49.32 167.57,61.16 169.2,94.44 168.92,97.33 167.57,124.8 168.69,128.48 169.8,132.17 172.56,136.29 173.62,138.85 173.94,138.98 174.05,139.26 173.92,139.57 174.47,140.91 175.65,142.08 175.98,142.08 J1.H1
LAN_SLED4_MDIN1: length 135.7
  IN2 w0.114: v1(170.26,36.37) 169.97,36.07 169.97,34.23 171.69,25.58 172.89,22.67 173.53,19.45 173.53,8.49 173.13,8.09 172.79,8.09 J9.E4
  BOTTOM w0.099: J1.K1 175.98,137.88 175.84,137.88 174.5,136.55 174.34,136.3 174.4,135.97 174.24,135.72 173.9,135.65 173.74,135.41 173.8,135.07 173.64,134.82 173.3,134.76 173.14,134.51 173.21,134.17 173.04,133.93 172.71,133.86 170.72,130.89 169.01,125.26 170.85,87.89 170.05,79.76 168.4,46.33 168.4,40.02 168.69,39.33 169.25,38.77 169.93,37.13 169.93,36.7 v1(170.26,36.37)
LAN_SLED4_MDIN2: length 133.9
  IN1 w0.114: J9.I4 171.81,12.71 171.65,12.71 171.38,12.99 171.38,18.31 169.08,29.87 168.92,31.49 169.18,31.81 169.15,32.16 168.83,32.42 168.8,32.77 169.06,33.09 169.02,33.44 168.7,33.7 168.66,34.12 168.92,34.44 168.89,34.79 168.57,35.05 168.45,36.27 168.75,36.99 169.69,38.4 169.95,39.02 169.95,39.46 v1(170.24,39.76)
  BOTTOM w0.099: J1.I2 177.98,140.78 177.84,140.78 177.72,140.67 177.72,136.06 177.02,134.36 176.54,133.65 174.74,131.85 171.91,127.62 170.65,124.56 172.41,88.57 172.17,86.14 169.91,40.09 v1(170.24,39.76)
LAN_SLED4_MDIN3: length 125.8
  TOP w0.099: J9.K4 171.78,16.52 171.49,16.52 171.18,16.83 171.18,22.1 170.7,32.03 170.7,32.88 171.18,37.84 171.18,40.24 171.7,41.49 171.7,42.18 v1(171.37,42.51)
  BOTTOM w0.099: J1.L2 179.02,136.58 179.16,136.58 179.26,136.48 179.26,135.46 178.81,134.36 175.24,130.8 172.55,126.77 171.7,124.72 172.79,102.64 173.78,92.52 171.7,50.23 171.7,47.13 171.46,46.89 171.46,46.59 171.7,46.35 171.7,46.05 171.46,45.81 171.46,45.52 171.7,45.27 171.7,44.98 171.46,44.74 171.46,44.44 171.7,44.2 171.7,42.85 v1(171.37,42.51)
LAN_SLED4_MDIP0: length 143.7
  BOTTOM w0.099: J1.G1 175.98,142.44 175.5,142.44 174.17,141.11 174.15,141.04 172.25,136.46 169.48,132.32 167.21,124.84 168.57,97.31 168.85,94.43 167.22,61.18 166.05,49.32 167.18,37.85 171.41,27.63 171.76,25.87 171.78,25.79 171.78,25.79 171.78,25.77 173.24,18.45 173.24,4.55 172.96,4.28 172.82,4.28 J9.C4
LAN_SLED4_MDIP1: length 135.7
  IN2 w0.114: v1(169.25,36.37) 169.54,36.07 169.54,34.19 171.03,26.71 170.8,26.37 170.87,26.02 171.21,25.79 171.28,25.45 171.8,24.21 171.64,23.83 171.77,23.5 172.15,23.34 172.49,22.54 172.71,21.41 172.48,21.06 172.55,20.72 172.89,20.49 173.11,19.41 173.11,8.67 172.95,8.51 172.79,8.51 J9.F4
  BOTTOM w0.099: J1.J1 175.98,138.24 175.69,138.24 174.22,136.77 170.4,131.05 168.66,125.3 170.49,87.9 169.69,79.79 168.05,46.34 168.05,39.95 168.39,39.13 168.95,38.57 169.58,37.06 169.58,36.7 v1(169.25,36.37)
LAN_SLED4_MDIP2: length 134.4
  IN1 w0.114: J9.H4 171.81,12.29 171.47,12.29 170.95,12.81 170.95,18.27 168.66,29.81 168.01,36.34 168.37,37.19 169.31,38.61 169.52,39.11 169.52,39.46 v1(169.23,39.76)
  BOTTOM w0.099: J1.H2 177.98,141.14 177.69,141.14 177.37,140.82 177.37,136.13 176.71,134.53 176.27,133.87 174.46,132.07 171.6,127.79 170.29,124.62 172.06,88.58 171.82,86.17 169.56,40.09 v1(169.23,39.76)
LAN_SLED4_MDIP3: length 125.8
  TOP w0.099: J9.L4 171.78,16.88 171.64,16.88 171.54,16.98 171.54,19.58 171.78,19.82 171.78,20.12 171.54,20.36 171.54,20.66 171.78,20.9 171.78,21.2 171.54,21.44 171.54,22.11 171.05,32.05 171.05,32.87 171.54,37.82 171.54,39.09 171.78,39.33 171.78,39.63 171.54,39.87 171.54,40.17 172.06,41.42 172.06,42.18 v1(172.39,42.51)
  BOTTOM w0.099: J1.K2 179.02,136.94 179.31,136.94 179.62,136.63 179.62,135.39 179.11,134.16 175.52,130.57 172.86,126.6 172.06,124.66 173.14,102.67 174.14,92.53 172.06,50.22 172.06,42.85 v1(172.39,42.51)
LAN_SLED5_MDIN0: length 140.2
  TOP w0.099: J9.B5 169.78,2.98 169.64,2.98 169.36,3.26 169.36,19.17 168.99,20.99 164.56,31.68 163.5,37.03 163.5,43.24 179.07,121.53 179.07,121.53 182.74,130.38 183.71,135.26 183.71,137.66 183.93,137.88 183.98,137.88 J1.K5
LAN_SLED5_MDIN1: length 137.1
  TOP w0.099: J1.K6 187.02,136.94 187.31,136.94 187.72,136.53 187.72,135.42 186.59,132.7 179.84,116.4 165.7,45.28 165.7,39.34 166.04,39 v1(166.04,38.99)
  BOTTOM w0.099: v1(166.04,38.99) 165.71,38.65 165.71,38.04 165.46,37.44 164.72,36.33 164.36,35.47 164.36,32.41 164.8,30.17 165.08,29.5 165.39,29.37 165.51,29.1 165.38,28.78 165.49,28.51 165.8,28.38 165.92,28.1 165.79,27.79 165.9,27.51 166.22,27.38 166.33,27.11 166.2,26.79 169.43,18.98 169.43,7.38 169.64,7.18 169.78,7.18 J9.E5
LAN_SLED5_MDIN2: length 133.7
  TOP w0.099: v1(165.02,35.33) 165.35,35.67 165.35,36.21 165.96,37.68 166.49,38.2 166.76,38.85 166.76,44.56 180.72,114.77 189.26,135.4 189.26,137.78 189.16,137.88 189.02,137.88 J1.K7
  BOTTOM w0.099: J9.H5 170.82,11.38 170.96,11.38 171.22,11.63 171.22,16.51 170.66,19.31 170.38,19.49 170.32,19.79 170.51,20.07 170.45,20.36 170.17,20.55 170.11,20.84 170.3,21.13 169.24,26.45 167.22,31.33 167.22,31.33 166.51,33.05 165.51,34.04 165.35,34.44 165.35,35 v1(165.02,35.33)
LAN_SLED5_MDIN3: length 128.3
  TOP w0.099: v1(165.04,32.54) 165.37,32.87 165.37,33.25 165.58,33.76 166.74,34.92 167.81,37.51 167.81,42.03 181.93,112.99 190.98,134.84 191.25,135.11 191.33,135.3 191.33,136.42 191.16,136.58 191.02,136.58 J1.L8
  IN2 w0.114: v1(165.04,32.54) 165.33,32.24 165.33,31.59 171.12,17.61 171.12,15.79 170.95,15.61 170.79,15.61 J9.K5
LAN_SLED5_MDIP0: length 141.3
  TOP w0.099: J9.A5 169.78,2.62 169.49,2.62 169,3.11 169,19.13 168.65,20.89 164.22,31.58 163.15,37 163.15,43.28 178.72,121.59 178.73,121.63 178.73,121.64 182.4,130.48 183.35,135.29 183.35,137.81 183.78,138.24 183.98,138.24 J1.J5
LAN_SLED5_MDIP1: length 136.9
  TOP w0.099: J1.L6 187.02,136.58 187.16,136.58 187.37,136.38 187.37,135.49 186.32,132.97 186.01,132.84 185.89,132.56 186.02,132.25 185.91,131.97 185.6,131.84 185.48,131.57 185.61,131.25 182.77,124.39 182.77,124.39 179.5,116.51 165.34,45.32 165.34,39.31 v1(165.02,38.99)
  BOTTOM w0.099: J9.D5 169.78,6.82 169.49,6.82 169.08,7.23 169.08,18.91 164.46,30.06 164,32.37 164,35.54 164.4,36.5 165.14,37.61 165.35,38.11 165.35,38.65 v1(165.02,38.99)
LAN_SLED5_MDIP2: length 134.5
  TOP w0.099: v1(166.04,35.33) 165.7,35.67 165.7,36.14 166.26,37.48 166.79,38 167.11,38.78 167.11,44.53 181.06,114.67 189.62,135.33 189.62,137.93 189.31,138.24 189.02,138.24 J1.J7
  BOTTOM w0.099: J9.G5 170.82,11.02 171.11,11.02 171.57,11.49 171.57,16.55 169.58,26.55 167.49,31.6 167.49,31.6 166.81,33.25 165.81,34.24 165.7,34.51 165.7,35 v1(166.04,35.33)
LAN_SLED5_MDIP3: length 129.6
  TOP w0.099: J1.K8 191.02,136.94 191.31,136.94 191.68,136.57 191.68,135.23 191.54,134.91 191.28,134.64 182.27,112.89 168.16,41.99 168.16,37.44 167.04,34.72 165.88,33.56 165.72,33.18 165.72,32.87 v1(166.06,32.54)
  IN2 w0.114: v1(166.06,32.54) 165.76,32.24 165.76,31.67 171.55,17.7 171.55,15.61 171.13,15.19 170.79,15.19 J9.J5
PD_PSU1_A0: length 25.9
  TOP w0.114: R2298.1 R2297.2 60.82,31.37 58.29,28.85 55.83,28.85 52.48,25.49 52.48,19.73 50.28,17.53 50.28,13.93 JP1.S1
PD_PSU1_A1: length 27.8
  TOP w0.114: JP1.S2 50.36,11.56 49.74,12.18 49.74,17.71 51.71,19.67 51.71,27.08 54.82,30.2 56.5,30.2 57.67,31.37 R13.2 R21.1
PD_PSU1_A2: length 39.9
  TOP w0.114: R15.2 R24.1 54.09,31.37 51.04,28.32 51.04,19.73 48.94,17.64 48.94,12.12 51.59,9.47 60.26,9.47 61.54,10.75 JP1.S9
PD_PSU1_PSON_N: length 4
  TOP w0.114: R39.1 56.46,16.31 JP1.S20
PD_PSU2_A0: length 19.3
  TOP w0.114: R23.2 130.39,28.42 130.4,28.41 R25.1 130.6,27.61 131.61,27.61 132.31,26.92 132.31,25.9 129.68,23.28 129.68,18.2 128.87,17.38 128.87,13.84 JP2.S1
PD_PSU2_A1: length 20.1
  TOP w0.114: R1.2 127.75,27.42 128.43,26.74 R37.1 129.26,26.37 129.26,18.5 128.39,17.63 128.39,12.48 129.31,11.56 JP2.S2
PD_PSU2_A2: length 35.7
  TOP w0.114: R40.1 130.39,30.62 130.39,30.61 R3.2 133.75,30.01 143.06,20.7 143.16,20.7 144.91,18.95 144.91,10.62 144.56,10.27 140.6,10.27 140.04,10.82 JP2.S9
PD_PSU2_PSON_N: length 3.6
  TOP w0.114: R41.1 134.96,18.93 JP2.S20
PSU1_HOTSTANDBYEN_H: length 22.5
  TOP w0.114: R38.2 v1(57.19,19.37)
  BOTTOM w0.114: JP1.S5 56.46,11.27 55.4,10.21 51.74,10.21 50.14,11.81 50.14,15.62 52.88,18.36 56.17,18.36 v1(57.19,19.37)
PSU1_ISHARE: length 26.1
  TOP w0.114: v1(57.44,22.76) R5.2
  BOTTOM w0.114: v1(57.44,22.76) 54.73,20.05 53.66,20.05 49.51,15.9 49.51,11.66 51.57,9.6 55.76,9.6 JP1.S6
PSU1_REMOTE_SENSE_P: length 139.1
  TOP w0.114: JP1.S17 60.27,17.69 59.24,18.72 56.67,18.72 55.21,20.17 v1(55.21,22.37) ; v1(92.79,132.45) 92.79,133.98 R26.2
  BOTTOM w0.114: v1(55.21,22.37) 56.56,23.72 56.56,89.75 92.79,125.99 v1(92.79,132.45)
PSU2_HOTSTANDBYEN_H: length 26.2
  TOP w0.114: v1(128.51,19.93) 128.51,19.2 127.95,18.65 127.95,12.13 129.72,10.36 134.15,10.36 134.96,11.17 JP2.S5 ; R6.2 v1(135.14,22.24)
  BOTTOM w0.114: v1(135.14,22.24) 132.83,19.93 v1(128.51,19.93)
PSU2_ISHARE: length 30
  TOP w0.114: v1(127.59,19.39) 127.49,19.29 127.49,18.55 127.48,18.54 127.48,12.03 129.54,9.96 134.63,9.96 JP2.S6 ; R7.2 v1(136.74,23.59)
  BOTTOM w0.114: v1(136.74,23.59) 136.74,22.74 133.4,19.39 v1(127.59,19.39)
PSU2_REMOTE_SENSE_P: length 130.7
  TOP w0.114: R27.2 v1(149.23,132.98) ; JP2.S17 138.77,23.52 v1(138.79,23.54)
  BOTTOM w0.114: v1(138.79,23.54) 141.69,23.54 147.64,29.49 147.64,36.53 155.16,44.04 155.16,127.05 v1(149.23,132.98)
PSU_HOTSTANDBYEN_H: length 79.1
  TOP w0.114: R38.1 v1(59.3,20.47) ; R6.1 v1(133.41,23.07)
  BOTTOM w0.114: v1(59.3,20.47) 60.61,19.16 80.28,19.16 84.92,23.81 132.67,23.81 v1(133.41,23.07)
PSU_ISHARE: length 79.7
  TOP w0.114: R7.1 v1(134.69,24.5) ; R5.1 v1(61,22.76)
  BOTTOM w0.114: v1(134.69,24.5) 133.25,24.5 133.25,24.5 84.64,24.5 79.97,19.84 63.92,19.84 v1(61,22.76)
PSU_REMOTE_SENSE_R: length 218.6
  TOP w0.114: JP1.S18 59,17.51 v1(58.57,17.94) ; R32.1 v1(93.98,132.29) ; v1(137.5,18.16) JP2.S18
  BOTTOM w0.114: v1(93.98,132.29) 93.38,131.69 93.38,125.74 56.82,89.18 56.82,25.6 58.57,23.85 v1(58.57,17.94) ; JP1.S18 61.12,17.5 80.24,17.5 82.4,19.65 124.76,19.65 125.86,18.55 137.11,18.55 v1(137.5,18.16)
PWR_PSU1_PWROK: length 25.9
  TOP w0.114: R29.2 R16.2 150.66,23.23 153.42,20.47 157.66,20.47 161.3,16.82 161.3,13.93 164.16,11.07 164.81,11.07 165.21,10.67 165.21,8.79 J9.E7
PWR_PSU1_PWROK_R: length 93
  TOP w0.114: R16.1 149.37,23.26 v1(149.05,22.93)
  BOTTOM w0.114: v1(149.05,22.93) 147.14,21.02 141.52,21.02 137.85,17.35 134.14,17.35 133.36,18.13 125.55,18.13 124.56,19.12 82.57,19.12 80.29,16.84 63.01,16.84 JP1.S16
PWR_PSU2_PWROK: length 24.5
  TOP w0.114: J9.G7 165.24,11.56 165.24,12.15 164.9,12.49 164.13,12.49 161.73,14.88 161.73,17.15 157.74,21.14 154.82,21.14 R31.2 R17.2
PWR_PSU2_PWROK_R: length 21.7
  TOP w0.114: R17.1 149.86,26.73 v1(150.58,27.45)
  BOTTOM w0.114: JP2.S16 140.04,16.82 140.83,17.61 147.33,17.61 150.58,20.86 v1(150.58,27.45)
SMB_BBU_ALERT_N: length 159.1
  IN2 w0.127: J1.A7 189.67,150.19 189.67,126.17 155.84,92.34 155.84,27.14 162.84,20.14 164.04,20.14 165.27,18.91 165.27,12.77 J9.H8
SMB_PDB_FRU_SCL: length 5
  TOP w0.114: U32.6 158.19,70.38 159.03,69.55 R1126.1
SMB_PDB_FRU_SDA: length 5
  TOP w0.114: U32.5 157.79,69.11 158.61,68.29 R1127.1
SMB_PMBUS_SCL: length 285.3
  TOP w0.114: R8.2 62.75,24.75 72.56,34.56 82.74,34.56 v1(94.75,22.55) ; R10.2 v1(130.89,22.11)
  IN2 w0.127: v1(130.89,22.11) 132.3,20.7 144.28,20.7 145.87,19.11 156.97,19.11 160.78,15.3 160.78,9.98 163.16,7.6 J9.E8 161.45,10.45 161.45,15.45 152.49,24.41 152.49,91.55 187.25,126.31 187.25,145.91 J1.D7
  BOTTOM w0.114: v1(130.89,22.11) 130.44,22.55 v1(94.75,22.55)
SMB_PMBUS_SDA: length 288.6
  TOP w0.114: R11.2 130.46,20.24 130.21,20.49 v1(130.21,20.79) ; v1(96.29,23.24) 83.92,35.61 71.61,35.61 62.72,26.72 R9.2
  IN2 w0.127: v1(130.21,20.79) 131.25,19.76 144.17,19.76 145.29,18.63 156.72,18.63 160.32,15.03 160.32,9.71 163.21,6.83 164.53,6.83 165.02,7.32 165.02,8.28 J9.F8 162.23,11.07 162.23,15.71 153.54,24.4 153.54,91.99 187.69,126.14 187.69,144.95 J1.E7
  BOTTOM w0.114: v1(96.29,23.24) 130.77,23.24 131.57,22.45 131.57,21.52 130.83,20.79 v1(130.21,20.79)
SMB_PSU1_SCL: length 12.6
  TOP w0.114: R8.1 56.11,24.75 53.96,22.6 53.96,19.97 52.65,18.66 JP1.S23
SMB_PSU1_SDA: length 13.5
  TOP w0.114: R9.1 53.31,23.49 53.31,19.9 51.38,17.97 JP1.S24
SMB_PSU2_SCL: length 9.6
  TOP w0.114: R10.1 133.17,21.33 133.29,21.21 133.29,19.23 131.15,17.1 JP2.S23
SMB_PSU2_SDA: length 6.4
  TOP w0.114: JP2.S24 129.88,16.73 132.4,19.25 132.4,19.96 132.12,20.24 R11.1
SMB_SLED_COMBINE_SCL: length 142.4
  TOP w0.114: J9.K8 165.05,16.75 165.05,19.58 160.51,24.13 160.51,30.98 162.16,32.63 162.16,68.65 v1(161.26,69.55) R1126.2
  IN1 w0.127: v1(161.26,69.55) 159.22,71.59 159.22,102.61 183.23,126.61 183.23,141.69 J1.G5
SMB_SLED_COMBINE_SDA: length 138.8
  TOP w0.114: R1127.2 v1(161.12,68.29) 161.42,67.98 161.42,32.78 160.03,31.39 160.03,23.14 163.58,19.59 163.58,18.12 J9.L8
  IN1 w0.127: v1(161.12,68.29) 161.9,69.07 161.9,70.53 159.73,72.7 159.73,102.4 183.72,126.38 183.72,140.78 J1.H5
TGND: length 71.2
  TOP w0.508: v1(204.22,57.31) 204.82,56.71 204.84,56.71 ; 209.93,107.82 v1(209.31,108.44) ; 209.93,107.82 J19.3 ; 209.93,107.82 209.91,107.82 v1(209.31,107.22) ; v1(205.52,107.22) 204.93,107.82 204.9,107.82 ; 213.23,157.07 213.21,157.07 v1(212.61,157.67) ; 213.23,157.07 v1(212.61,156.45) ; 213.23,157.07 J31.3 ; J26.3 213.19,239.03 ; J26.3 v1(213.22,238.13) ; J26.3 213.24,239.03 ; 213.19,239.03 v1(212.57,238.41) ; 213.19,239.03 213.17,239.03 v1(212.57,239.63) ; J31.3 v1(213.26,156.17) ; J31.3 213.28,157.07 ; J19.3 209.98,107.82 ; J19.3 v1(209.96,108.72) ; 209.98,107.82 v1(210.6,108.44) ; 209.98,107.82 210.01,107.82 v1(210.6,107.22) ; J20.3 v1(204.88,108.72) ; J20.3 204.85,107.82 ; J20.3 204.9,107.82 ; 204.85,107.82 204.83,107.82 v1(204.23,107.22) ; 204.85,107.82 v1(204.23,108.44) ; 204.9,107.82 v1(205.52,108.44) ; 213.28,225.5 v1(213.9,226.13) ; 213.28,225.5 213.31,225.5 v1(213.9,224.91) ; 213.28,225.5 J25.3 ; J14.3 204.84,56.71 ; J14.3 204.9,56.71 ; J14.3 v1(204.87,55.81) ; 204.84,56.71 v1(204.22,56.09) ; 213.23,225.5 213.2,225.5 v1(212.61,224.91) ; 213.23,225.5 v1(212.61,226.13) ; 213.23,225.5 J25.3 ; 204.9,56.71 v1(205.52,56.09) ; 204.9,56.71 204.92,56.71 v1(205.52,57.31) ; v1(212.57,301.79) 213.16,302.39 213.19,302.39 ; 209.92,56.71 v1(209.3,56.09) ; 209.92,56.71 209.9,56.71 v1(209.3,57.31) ; 209.92,56.71 J13.3 ; v1(213.86,301.79) 213.27,302.39 213.24,302.39 ; v1(210.6,57.31) 210,56.71 209.98,56.71 ; 209.98,56.71 v1(210.6,56.09) ; 209.98,56.71 J13.3 ; 213.19,302.39 J32.3 ; 213.19,302.39 v1(212.57,303.01) ; J32.3 v1(213.21,303.29) ; J32.3 213.24,302.39 ; 213.24,239.03 v1(213.87,238.41) ; 213.24,239.03 213.27,239.03 v1(213.87,239.63) ; J25.3 v1(213.25,226.4) ; J13.3 v1(209.95,55.81) ; 213.28,157.07 213.31,157.07 v1(213.91,157.67) ; 213.28,157.07 v1(213.91,156.45) ; 213.24,302.39 v1(213.86,303.01)
  BOTTOM w0.508: J27.3 v1(215.79,226.4) ; J27.3 215.82,225.5 ; J27.3 215.77,225.5 ; v1(211.85,107.22) 212.45,107.82 212.47,107.82 ; 207.39,107.82 207.37,107.82 v1(206.77,107.22) ; 207.39,107.82 J21.3 ; 207.39,107.82 v1(206.77,108.44) ; 207.38,56.71 207.36,56.71 v1(206.76,57.31) ; 207.38,56.71 v1(206.76,56.09) ; 207.38,56.71 J15.3 ; 212.46,56.71 v1(211.84,56.09) ; 212.46,56.71 212.44,56.71 v1(211.84,57.31) ; 212.46,56.71 J12.3 ; v1(215.11,239.63) 215.71,239.03 215.73,239.03 ; 212.52,56.71 v1(213.14,56.09) ; 212.52,56.71 J12.3 ; 212.52,56.71 212.54,56.71 v1(213.14,57.31) ; 212.52,107.82 v1(213.14,108.44) ; 212.52,107.82 212.55,107.82 v1(213.14,107.22) ; 212.52,107.82 J18.3 ; J33.3 215.82,157.07 ; J33.3 215.77,157.07 ; J33.3 v1(215.8,156.17) ; 215.82,157.07 v1(216.45,156.45) ; 215.82,157.07 215.85,157.07 v1(216.45,157.67) ; 212.47,107.82 J18.3 ; 212.47,107.82 v1(211.85,108.44) ; J30.3 v1(215.76,238.13) ; J30.3 215.73,239.03 ; J30.3 215.78,239.03 ; J24.3 215.78,302.39 ; J24.3 v1(215.75,303.29) ; J24.3 215.73,302.39 ; 215.78,302.39 v1(216.4,303.01) ; 215.78,302.39 215.81,302.39 v1(216.4,301.79) ; 215.73,239.03 v1(215.11,238.41) ; 215.82,225.5 v1(216.44,226.13) ; 215.82,225.5 215.85,225.5 v1(216.44,224.91) ; v1(216.41,239.63) 215.81,239.03 215.78,239.03 ; 215.77,157.07 v1(215.15,156.45) ; 215.77,157.07 215.75,157.07 v1(215.15,157.67) ; J18.3 v1(212.5,108.72) ; J12.3 v1(212.49,55.81) ; J21.3 v1(207.42,108.72) ; J21.3 207.44,107.82 ; J15.3 207.44,56.71 ; J15.3 v1(207.41,55.81) ; 207.44,56.71 207.46,56.71 v1(208.06,57.31) ; 207.44,56.71 v1(208.06,56.09) ; 215.77,225.5 v1(215.15,226.13) ; 215.77,225.5 215.74,225.5 v1(215.15,224.91) ; 215.73,302.39 v1(215.11,303.01) ; 215.73,302.39 215.7,302.39 v1(215.11,301.79) ; 215.78,239.03 v1(216.41,238.41) ; v1(208.06,107.22) 207.47,107.82 207.44,107.82 ; 207.44,107.82 v1(208.06,108.44)
  vias: v1(201.45,113.59) v1(201.45,111.05) v1(201.45,108.51) v1(201.45,105.97) v1(201.45,103.43) v1(201.45,100.89) v1(201.45,98.35) v1(201.45,95.81) v1(201.45,93.27) v1(201.45,90.73) v1(201.45,88.19) v1(201.45,85.65) v1(201.45,83.11) v1(201.45,80.57) v1(201.45,78.03) v1(201.45,75.49) v1(201.45,72.95) v1(201.45,70.41) v1(201.45,67.87) v1(201.45,65.33) v1(201.45,62.79) v1(201.45,60.25) v1(201.45,57.71) v1(201.45,55.02) v1(201.61,52.31) v1(203.54,50.04) v1(203.58,114.7) v1(205.82,114.7) v1(206.31,50.01) v1(208.31,114.73) v1(208.96,49.98) v1(210.09,306.14) v1(210.09,303.6) v1(210.09,301.06) v1(210.09,298.52) v1(210.09,295.98) v1(210.09,293.44) v1(210.09,290.9) v1(210.09,288.36) v1(210.09,285.82) v1(210.09,283.28) v1(210.09,280.74) v1(210.09,278.2) v1(210.09,275.66) v1(210.09,273.12) v1(210.09,270.58) v1(210.09,268.04) v1(210.09,265.5) v1(210.09,262.96) v1(210.09,260.42) v1(210.09,257.88) v1(210.09,255.34) v1(210.09,252.8) v1(210.09,250.26) v1(210.09,247.72) v1(210.09,245.18) v1(210.09,242.64) v1(210.09,240.1) v1(210.09,237.56) v1(210.09,235.02) v1(210.09,232.48) v1(210.09,229.94) v1(210.09,227.4) v1(210.09,224.86) v1(210.09,222.32) v1(210.09,219.78) v1(210.09,217.24) v1(210.09,214.7) v1(210.09,212.16) v1(210.09,209.62) v1(210.09,207.08) v1(210.09,204.54) v1(210.09,202) v1(210.09,199.46) v1(210.09,196.92) v1(210.09,194.38) v1(210.09,191.84) v1(210.09,189.3) v1(210.09,186.76) v1(210.09,184.22) v1(210.09,181.68) v1(210.09,179.14) v1(210.09,176.6) v1(210.09,174.06) v1(210.09,171.52) v1(210.09,168.98) v1(210.09,166.44) v1(210.09,163.9) v1(210.09,161.36) v1(210.09,158.82) v1(210.09,156.28) v1(210.12,153.66) v1(210.19,150.98) v1(210.74,308.87) v1(210.74,114.76) v1(211.75,49.89) v1(212.61,150.74) v1(213.28,308.87) v1(213.54,114.79) v1(214.24,50.07) v1(214.89,150.74) v1(215.72,113.84) v1(215.72,111.3) v1(215.72,108.76) v1(215.72,106.22) v1(215.72,103.68) v1(215.72,101.14) v1(215.72,98.6) v1(215.72,96.06) v1(215.72,93.52) v1(215.72,90.98) v1(215.72,88.44) v1(215.72,85.9) v1(215.72,83.36) v1(215.72,80.82) v1(215.72,78.28) v1(215.72,75.74) v1(215.72,73.2) v1(215.72,70.66) v1(215.72,68.12) v1(215.72,65.58) v1(215.72,63.04) v1(215.72,60.5) v1(215.72,57.96) v1(215.69,55.42) v1(215.69,52.47) v1(215.82,308.87) v1(217.57,150.68) v1(218.36,308.87) v1(218.67,152.09) v1(218.89,154.77) v1(219.04,307.49) v1(219.04,304.95) v1(219.04,302.41) v1(219.04,299.87) v1(219.04,297.33) v1(219.04,294.79) v1(219.04,292.25) v1(219.04,289.71) v1(219.04,287.17) v1(219.04,284.63) v1(219.04,282.09) v1(219.04,279.55) v1(219.04,277.01) v1(219.04,274.47) v1(219.04,271.93) v1(219.04,269.39) v1(219.04,266.85) v1(219.04,264.31) v1(219.04,261.77) v1(219.04,259.23) v1(219.04,256.69) v1(219.04,254.15) v1(219.04,251.61) v1(219.04,249.07) v1(219.04,246.53) v1(219.04,243.99) v1(219.04,241.45) v1(219.04,238.91) v1(219.04,236.37) v1(219.04,233.83) v1(219.04,231.29) v1(219.04,228.75) v1(219.04,226.21) v1(219.04,223.67) v1(219.04,221.13) v1(219.04,218.59) v1(219.04,216.05) v1(219.04,213.51) v1(219.04,210.97) v1(219.04,208.43) v1(219.04,205.89) v1(219.04,203.35) v1(219.04,200.81) v1(219.04,198.27) v1(219.04,195.73) v1(219.04,193.19) v1(219.04,190.65) v1(219.04,188.11) v1(219.04,185.57) v1(219.04,183.03) v1(219.04,180.49) v1(219.04,177.95) v1(219.04,175.41) v1(219.04,172.87) v1(219.04,170.33) v1(219.04,167.79) v1(219.04,165.25) v1(219.04,162.71) v1(219.04,160.17) v1(219.04,157.63)
